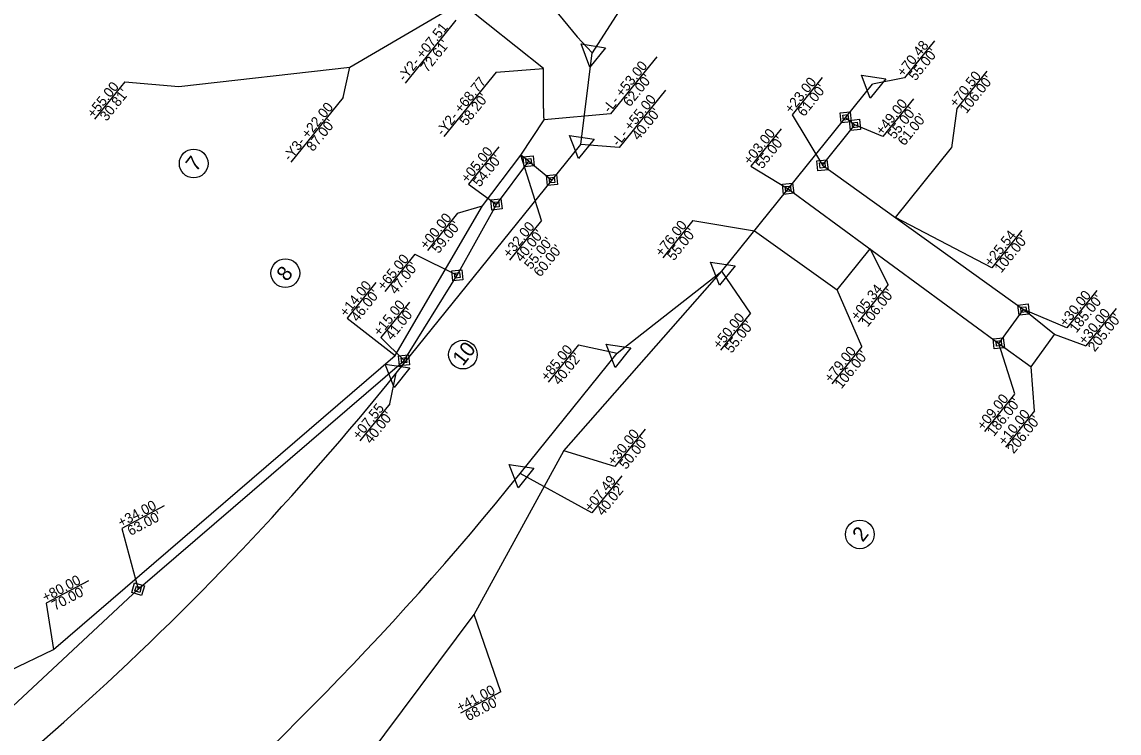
# Model space of a CAD drawing. Extents: x 1487704 to 1489071, y 498271 to 499440.
# Drawn here: x 1488354 to 1488904, y 498758 to 499115 of the extents above; entities that cross this region are included whole.
import ezdxf

# ---------------------------------------------------------------- set-up
doc = ezdxf.new("R2010")
doc.units = 0
for name, color, linetype in [('Prop Easement Construction', 7, 'Continuous'), ('Prop Easement Construction Station Offsets', 7, 'Continuous'), ('Prop Easement Permanent Drainage', 7, 'Continuous'), ('Prop Easement Permanent Drainage Station Offsets', 7, 'Continuous'), ('Prop Easement Temporary Drainage', 7, 'Continuous'), ('Prop Easement Temporary Drainage Station Offsets', 7, 'Continuous'), ('Prop ROW Marker CELL', 7, 'Continuous'), ('Prop ROW Permanent Easement CELL', 7, 'Continuous'), ('Prop ROW RW Lines', 7, 'Continuous'), ('Prop ROW Station Offsets', 7, 'Continuous'), ('Prop ROW Text', 7, 'Continuous')]:
    doc.layers.add(name, color=color, linetype=linetype)

msp = doc.modelspace()

# ---------------------------------------------------------------- linework, layer by layer
at = {"layer": 'Prop Easement Construction'}
for p, q in [((1488518.15, 499091.88), (1488573.75, 499124.4)), ((1488615.46, 499091.23), (1488573.75, 499124.4)), ((1488432.36, 499082.13), (1488518.15, 499091.88)), ((1488604.07, 499047.81), (1488615.7, 499065.41)), ((1488607.97, 499044.67), (1488604.07, 499047.81)), ((1488792.01, 499016.41), (1488820.23, 499051.41)), ((1488721.21, 499009.87), (1488762.79, 498980.19)), ((1488762.79, 498980.19), (1488779.33, 499000.69)), ((1488625.67, 498899.36), (1488704.89, 498989.63)), ((1488871.87, 498957.74), (1488856.3, 498970.29)), ((1488843.9, 498953.32), (1488860.1, 498941.54)), ((1488860.1, 498941.54), (1488871.87, 498957.74)), ((1488580.63, 498817.39), (1488625.67, 498899.36)), ((1488507.15, 498718.97), (1488580.63, 498817.39))]:
    msp.add_line(p, q, dxfattribs=at)
msp.add_spline([(1488615.7, 499065.41), (1488615.68, 499065.76), (1488615.67, 499066.11), (1488615.65, 499066.46), (1488615.64, 499066.82), (1488615.63, 499067.17), (1488615.61, 499067.52), (1488615.6, 499067.87), (1488615.59, 499068.22), (1488615.57, 499068.58), (1488615.56, 499068.93), (1488615.55, 499069.28), (1488615.54, 499069.63), (1488615.53, 499069.98), (1488615.52, 499070.33), (1488615.5, 499070.69), (1488615.49, 499071.04), (1488615.48, 499071.39), (1488615.47, 499071.74), (1488615.47, 499072.09), (1488615.46, 499072.44), (1488615.45, 499072.79), (1488615.44, 499073.14), (1488615.43, 499073.49), (1488615.42, 499073.84), (1488615.42, 499074.19), (1488615.41, 499074.54), (1488615.4, 499074.89), (1488615.4, 499075.24), (1488615.39, 499075.59), (1488615.38, 499075.94), (1488615.38, 499076.29), (1488615.37, 499076.64), (1488615.37, 499076.99), (1488615.36, 499077.34), (1488615.36, 499077.69), (1488615.36, 499078.04), (1488615.35, 499078.39), (1488615.35, 499078.74), (1488615.35, 499079.09), (1488615.35, 499079.44), (1488615.34, 499079.79), (1488615.34, 499080.13), (1488615.34, 499080.48), (1488615.34, 499080.83), (1488615.34, 499081.18), (1488615.34, 499081.53), (1488615.34, 499081.88), (1488615.34, 499082.22), (1488615.34, 499082.57), (1488615.34, 499082.92), (1488615.34, 499083.27), (1488615.34, 499083.61), (1488615.34, 499083.96), (1488615.35, 499084.31), (1488615.35, 499084.66), (1488615.35, 499085), (1488615.36, 499085.35), (1488615.36, 499085.7), (1488615.36, 499086.04), (1488615.37, 499086.39), (1488615.37, 499086.74), (1488615.38, 499087.08), (1488615.38, 499087.43), (1488615.39, 499087.78), (1488615.39, 499088.12), (1488615.4, 499088.47), (1488615.41, 499088.81), (1488615.41, 499089.16), (1488615.42, 499089.5), (1488615.43, 499089.85), (1488615.43, 499090.19), (1488615.44, 499090.54), (1488615.46, 499091.23)], degree=3, dxfattribs=at)
at = {"layer": 'Prop Easement Construction Station Offsets'}
for p, q in [((1488571.39, 499115.4), (1488545.91, 499083.92)), ((1488672.29, 499097.14), (1488649.05, 499068.42)), ((1488591.69, 499089.46), (1488565.47, 499057.05)), ((1488837.94, 499089.85), (1488822.85, 499071.13)), ((1488405.29, 499084.48), (1488390.16, 499065.78)), ((1488514.87, 499076.63), (1488488.64, 499044.21)), ((1488690.33, 499014.98), (1488675.24, 498996.26)), ((1488855.42, 499009.88), (1488840.36, 498991.21)), ((1488788.35, 498982.79), (1488773.3, 498964.12)), ((1488902.73, 498970.82), (1488887.63, 498952.1)), ((1488775.23, 498951.78), (1488760.13, 498933.06)), ((1488861.86, 498919.42), (1488847.21, 498901.25)), ((1488666.35, 498910.29), (1488651.26, 498891.57)), ((1488593.97, 498778.52), (1488573.76, 498767.85))]:
    msp.add_line(p, q, dxfattribs=at)
for points in [[(1488514.87, 499076.63), (1488518.15, 499091.88), (1488518.15, 499091.88)], [(1488591.69, 499089.46), (1488615.46, 499091.23), (1488615.46, 499091.23)], [(1488405.29, 499084.48), (1488432.36, 499082.13)], [(1488649.05, 499068.42), (1488615.7, 499065.41)], [(1488822.85, 499071.13), (1488820.23, 499051.41), (1488820.23, 499051.41)], [(1488690.33, 499014.98), (1488721.21, 499009.87)], [(1488840.36, 498991.21), (1488792.01, 499016.41), (1488792.01, 499016.41)], [(1488788.35, 498982.79), (1488779.33, 499000.69), (1488779.33, 499000.69)], [(1488775.23, 498951.78), (1488762.79, 498980.19), (1488762.79, 498980.19)], [(1488887.77, 498951.99), (1488871.87, 498957.74)], [(1488861.86, 498919.42), (1488860.1, 498941.54)], [(1488651.26, 498891.57), (1488625.67, 498899.36), (1488625.67, 498899.36)], [(1488593.97, 498778.52), (1488580.63, 498817.39), (1488580.63, 498817.39)]]:
    msp.add_lwpolyline(points, dxfattribs=at)
at = {"layer": 'Prop Easement Permanent Drainage'}
for p, q in [((1488755.39, 499042.69), (1488771.71, 499062.92)), ((1488767.04, 499066.69), (1488771.71, 499062.92)), ((1488591.79, 499023.02), (1488607.97, 499044.67)), ((1488607.97, 499044.67), (1488619.64, 499035.25)), ((1488755.39, 499042.69), (1488856.3, 498970.29)), ((1488738.16, 499030.88), (1488843.9, 498953.32)), ((1488572.13, 498987.49), (1488591.79, 499023.02)), ((1488545.42, 498944.81), (1488572.13, 498987.49)), ((1488843.9, 498953.32), (1488856.3, 498970.29)), ((1488411.92, 498830), (1488545.42, 498944.81)), ((1488341.17, 498764.08), (1488411.92, 498830))]:
    msp.add_line(p, q, dxfattribs=at)
at = {"layer": 'Prop Easement Permanent Drainage Station Offsets'}
for p, q in [((1488755.29, 499086.77), (1488740.19, 499068.05)), ((1488801.04, 499076.03), (1488785.76, 499057.08)), ((1488734.63, 499061.02), (1488719.53, 499042.3)), ((1488592.93, 499051.92), (1488577.8, 499033.23)), ((1488550.87, 498998.02), (1488535.75, 498979.32)), ((1488893.11, 498979.81), (1488878.02, 498961.09)), ((1488548.15, 498974.09), (1488533.78, 498956.33)), ((1488851.73, 498927.9), (1488836.64, 498909.18)), ((1488425.03, 498871.78), (1488403.77, 498860.55))]:
    msp.add_line(p, q, dxfattribs=at)
for points in [[(1488740.19, 499068.05), (1488755.39, 499042.69)], [(1488785.76, 499057.08), (1488771.71, 499062.92)], [(1488719.53, 499042.3), (1488738.16, 499030.88)], [(1488577.8, 499033.23), (1488591.79, 499023.02)], [(1488550.87, 498998.02), (1488572.13, 498987.49)], [(1488878.02, 498961.09), (1488856.3, 498970.29), (1488856.3, 498970.29)], [(1488533.78, 498956.33), (1488545.42, 498944.81)], [(1488851.94, 498928.01), (1488843.9, 498953.32), (1488843.9, 498953.32)], [(1488403.77, 498860.55), (1488411.92, 498830)]]:
    msp.add_lwpolyline(points, dxfattribs=at)
at = {"layer": 'Prop Easement Temporary Drainage'}
for p, q in [((1488584.76, 499022.27), (1488604.07, 499047.81)), ((1488540.9, 498947.17), (1488584.76, 499022.27)), ((1488369.59, 498799.74), (1488540.9, 498947.17)), ((1488347.21, 498789.14), (1488369.59, 498799.74))]:
    msp.add_line(p, q, dxfattribs=at)
at = {"layer": 'Prop Easement Temporary Drainage Station Offsets'}
for p, q in [((1488572.24, 499018.6), (1488557.14, 498999.89)), ((1488614.39, 499014.9), (1488598.37, 498995.03)), ((1488531.25, 498983.8), (1488516.91, 498966.01)), ((1488387.05, 498834.26), (1488365.78, 498823.03))]:
    msp.add_line(p, q, dxfattribs=at)
for points in [[(1488614.39, 499014.9), (1488604.07, 499047.81)], [(1488572.24, 499018.6), (1488584.76, 499022.27)], [(1488516.91, 498966.01), (1488540.9, 498947.17)], [(1488365.78, 498823.03), (1488369.59, 498799.74)]]:
    msp.add_lwpolyline(points, dxfattribs=at)
at = {"layer": 'Prop ROW Marker CELL'}
for p, q in [((1488639.84, 499099.01), (1488639.84, 499099.01)), ((1488780.52, 499083.41), (1488780.52, 499083.41)), ((1488767.04, 499066.69), (1488767.04, 499066.69)), ((1488771.71, 499062.92), (1488771.71, 499062.92)), ((1488634.08, 499053.16), (1488634.08, 499053.16)), ((1488607.97, 499044.67), (1488607.97, 499044.67)), ((1488755.39, 499042.69), (1488755.39, 499042.69)), ((1488619.64, 499035.25), (1488619.64, 499035.25)), ((1488738.16, 499030.88), (1488738.16, 499030.88)), ((1488591.79, 499023.02), (1488591.79, 499023.02)), ((1488572.13, 498987.49), (1488572.13, 498987.49)), ((1488704.89, 498989.63), (1488704.89, 498989.63)), ((1488856.3, 498970.29), (1488856.3, 498970.29)), ((1488843.9, 498953.32), (1488843.9, 498953.32)), ((1488652.43, 498948.43), (1488652.43, 498948.43)), ((1488545.42, 498944.81), (1488545.42, 498944.81)), ((1488541.53, 498938.4), (1488541.53, 498938.4)), ((1488603.75, 498888.08), (1488603.75, 498888.08)), ((1488411.92, 498830), (1488411.92, 498830))]:
    msp.add_line(p, q, dxfattribs=at)
for points in [[(1488638.72, 499091.88), (1488634.24, 499103.53), (1488646.57, 499101.61)], [(1488779.4, 499076.29), (1488774.92, 499087.93), (1488787.25, 499086.02)], [(1488632.96, 499046.03), (1488628.48, 499057.68), (1488640.81, 499055.76)], [(1488703.77, 498982.5), (1488699.29, 498994.15), (1488711.62, 498992.23)], [(1488651.31, 498941.31), (1488646.82, 498952.95), (1488659.15, 498951.04)], [(1488540.41, 498931.27), (1488535.93, 498942.92), (1488548.26, 498941)], [(1488602.63, 498880.95), (1488598.15, 498892.6), (1488610.48, 498890.68)]]:
    msp.add_lwpolyline(points, close=True, dxfattribs=at)
at = {"layer": 'Prop ROW Permanent Easement CELL'}
for points in [[(1488764.24, 499068.95), (1488769.3, 499069.49), (1488769.84, 499064.43), (1488764.78, 499063.89)], [(1488765.64, 499067.82), (1488768.17, 499068.09), (1488768.44, 499065.56), (1488765.91, 499065.29)], [(1488768.91, 499065.18), (1488773.97, 499065.73), (1488774.51, 499060.66), (1488769.45, 499060.12)], [(1488770.31, 499064.05), (1488772.84, 499064.32), (1488773.11, 499061.79), (1488770.58, 499061.52)], [(1488605.16, 499046.93), (1488610.23, 499047.47), (1488610.77, 499042.41), (1488605.71, 499041.87)], [(1488606.56, 499045.8), (1488609.1, 499046.07), (1488609.37, 499043.54), (1488606.84, 499043.27)], [(1488752.58, 499044.94), (1488757.65, 499045.49), (1488758.19, 499040.43), (1488753.13, 499039.88)], [(1488753.99, 499043.82), (1488756.52, 499044.09), (1488756.79, 499041.56), (1488754.26, 499041.28)], [(1488616.84, 499037.51), (1488621.9, 499038.05), (1488622.44, 499032.99), (1488617.38, 499032.45)], [(1488618.24, 499036.38), (1488620.77, 499036.65), (1488621.04, 499034.12), (1488618.51, 499033.85)], [(1488735.36, 499033.14), (1488740.42, 499033.69), (1488740.96, 499028.62), (1488735.9, 499028.08)], [(1488736.76, 499032.01), (1488739.29, 499032.28), (1488739.56, 499029.75), (1488737.03, 499029.48)], [(1488588.99, 499025.28), (1488594.05, 499025.83), (1488594.6, 499020.76), (1488589.53, 499020.22)], [(1488590.39, 499024.15), (1488592.92, 499024.42), (1488593.2, 499021.89), (1488590.66, 499021.62)], [(1488569.33, 498989.75), (1488574.39, 498990.29), (1488574.94, 498985.23), (1488569.87, 498984.69)], [(1488570.73, 498988.62), (1488573.26, 498988.89), (1488573.53, 498986.36), (1488571, 498986.09)], [(1488853.5, 498972.55), (1488858.56, 498973.1), (1488859.11, 498968.03), (1488854.04, 498967.49)], [(1488854.9, 498971.42), (1488857.43, 498971.69), (1488857.71, 498969.16), (1488855.17, 498968.89)], [(1488841.1, 498955.58), (1488846.16, 498956.12), (1488846.7, 498951.06), (1488841.64, 498950.52)], [(1488842.5, 498954.45), (1488845.03, 498954.72), (1488845.3, 498952.19), (1488842.77, 498951.92)], [(1488542.61, 498947.07), (1488547.68, 498947.61), (1488548.22, 498942.55), (1488543.16, 498942)], [(1488544.02, 498945.94), (1488546.55, 498946.21), (1488546.82, 498943.68), (1488544.29, 498943.4)], [(1488410.24, 498833.18), (1488415.1, 498831.68), (1488413.6, 498826.82), (1488408.74, 498828.32)], [(1488411.08, 498831.59), (1488413.51, 498830.84), (1488412.76, 498828.41), (1488410.33, 498829.16)]]:
    msp.add_lwpolyline(points, close=True, dxfattribs=at)
at = {"layer": 'Prop ROW RW Lines'}
for p, q in [((1488634.08, 499053.16), (1488639.84, 499099.01)), ((1488704.89, 498989.63), (1488780.52, 499083.41)), ((1488541.53, 498938.4), (1488634.08, 499053.16)), ((1488652.43, 498948.43), (1488704.89, 498989.63)), ((1488603.75, 498888.08), (1488652.43, 498948.43))]:
    msp.add_line(p, q, dxfattribs=at)
for centre, radius, start, end in [((1488809.02, 499262.12), 235, 195.2846, 223.9537), ((1487403.1, 499856.48), 1462.5, 302.71583, 321.11571), ((1487403.1, 499856.44), 1542.5, 297.83218, 321.11298)]:
    msp.add_arc(centre, radius, start, end, dxfattribs=at)
at = {"layer": 'Prop ROW Station Offsets'}
for p, q in [((1488811.6, 499105.18), (1488796.55, 499086.52)), ((1488676.67, 499080.31), (1488653.43, 499051.59)), ((1488719.25, 498968.57), (1488704.15, 498949.85)), ((1488632.92, 498952.55), (1488617.82, 498933.83)), ((1488538.26, 498923.02), (1488523.27, 498904.43)), ((1488654.73, 498886.92), (1488639.71, 498868.3))]:
    msp.add_line(p, q, dxfattribs=at)
for points in [[(1488668.08, 499143.3), (1488639.84, 499099.01)], [(1488796.55, 499086.52), (1488780.52, 499083.41), (1488780.52, 499083.41)], [(1488653.43, 499051.59), (1488634.08, 499053.16)], [(1488719.25, 498968.57), (1488704.89, 498989.63), (1488704.89, 498989.63)], [(1488632.92, 498952.55), (1488652.43, 498948.43), (1488652.43, 498948.43)], [(1488538.26, 498923.02), (1488541.53, 498938.4)], [(1488639.71, 498868.3), (1488603.75, 498888.08)]]:
    msp.add_lwpolyline(points, dxfattribs=at)
at = {"layer": 'Prop ROW Text'}
for p, q in [((1488439.86, 499043.58), (1488439.86, 499043.58)), ((1488485.85, 498988.57), (1488485.85, 498988.57)), ((1488574.98, 498947.7), (1488574.98, 498947.7)), ((1488774.15, 498857.51), (1488774.15, 498857.51))]:
    msp.add_line(p, q, dxfattribs=at)
for centre in [(1488439.86, 499043.58), (1488485.85, 498988.57), (1488574.98, 498947.7), (1488774.15, 498857.51)]:
    msp.add_circle(centre, 7.2, dxfattribs=at)

# ---------------------------------------------------------------- texts
at = {"layer": 'Prop Easement Construction Station Offsets'}
for s, rotation, p in [('-Y2- +07.51', 51.0257, (1488545.68, 499084.42)), ("72.61'", 51.0257, (1488557.09, 499088.98)), ('-L- +53.00', 51.0257, (1488648.57, 499068.62)), ('-Y2- +68.77', 51.0257, (1488564.91, 499057.16)), ("62.00'", 51.0257, (1488658.73, 499071.64)), ('+70.50', 51.1156, (1488822.37, 499071.33)), ("106.00'", 51.1156, (1488827.61, 499068.27)), ('+55.00', 51.0257, (1488389.68, 499065.98)), ("30.81'", 51.0257, (1488396.16, 499064.45)), ('-Y3- +22.00', 51.0257, (1488488.16, 499044.41)), ("58.20'", 51.0257, (1488576.64, 499062.11)), ("87.00'", 51.0257, (1488499.81, 499049.28)), ('+76.00', 51.1156, (1488674.76, 498996.46)), ("55.00'", 51.1156, (1488680.86, 498994.47)), ('+25.54', 51.1156, (1488839.95, 498991.49)), ("106.00'", 51.1156, (1488845.1, 498988.33)), ('+05.34', 51.1156, (1488772.88, 498964.4)), ("106.00'", 51.1156, (1488778.04, 498961.23)), ('+30.00', 51.1156, (1488887.15, 498952.3)), ("205.00'", 51.1156, (1488892.02, 498948.77)), ('+79.00', 51.1156, (1488759.65, 498933.26)), ("106.00'", 51.1156, (1488764.89, 498930.2)), ('+10.00', 51.1156, (1488846.88, 498901.64)), ("206.00'", 51.1156, (1488851.37, 498897.65)), ('+30.00', 51.1156, (1488650.78, 498891.77)), ("50.00'", 51.1156, (1488656.88, 498889.78)), ('+41.00', 27.8351, (1488573.4, 498768.22)), ("68.00'", 27.8351, (1488577.69, 498763.7))]:
    msp.add_text(s, height=5, rotation=rotation, dxfattribs=at).set_placement(p)
at = {"layer": 'Prop Easement Permanent Drainage Station Offsets'}
for s, rotation, p in [('+23.00', 51.1156, (1488739.71, 499068.25)), ("61.00'", 51.1156, (1488746.19, 499066.73)), ('+49.00', 51.1156, (1488785.37, 499057.39)), ("55.00'", 51.1156, (1488791.47, 499055.41)), ("61.00'", 51.1156, (1488796.52, 499052.11)), ('+03.00', 51.1156, (1488719.05, 499042.5)), ("55.00'", 51.1156, (1488725.16, 499040.51)), ('+05.00', 51.0257, (1488577.32, 499033.43)), ("54.00'", 51.0257, (1488583.42, 499031.43)), ('+65.00', 51.0257, (1488535.27, 498979.52)), ("47.00'", 51.0257, (1488541.37, 498977.53)), ('+15.00', 51.0257, (1488533.3, 498956.53)), ('+30.00', 51.1156, (1488877.53, 498961.29)), ("185.00'", 51.1156, (1488882.77, 498958.23)), ("41.00'", 51.0257, (1488539.4, 498954.53)), ('+09.00', 51.1156, (1488836.16, 498909.38)), ("186.00'", 51.1156, (1488841.39, 498906.32)), ('+34.00', 27.8351, (1488403.4, 498860.92)), ("63.00'", 27.8351, (1488408.22, 498856.68))]:
    msp.add_text(s, height=5, rotation=rotation, dxfattribs=at).set_placement(p)
at = {"layer": 'Prop Easement Temporary Drainage Station Offsets'}
for s, rotation, p in [('+00.00', 51.1156, (1488556.66, 499000.09)), ("59.00'", 51.1156, (1488562.77, 498998.1)), ('+32.00', 51.1156, (1488598.35, 498995.8)), ("40.00'", 51.1156, (1488604.46, 498993.81)), ("55.00'", 51.1156, (1488609.13, 498990.05)), ("60.00'", 51.1156, (1488613.8, 498986.28)), ('+14.00', 51.1156, (1488516.43, 498966.21)), ("46.00'", 51.1156, (1488522.15, 498963.76)), ('+80.00', 27.8351, (1488365.42, 498823.4)), ("70.00'", 27.8351, (1488370.24, 498819.17))]:
    msp.add_text(s, height=5, rotation=rotation, dxfattribs=at).set_placement(p)
at = {"layer": 'Prop ROW Station Offsets'}
for s, rotation, p in [('+70.48', 51.1156, (1488796.05, 499086.69)), ("55.00'", 51.1156, (1488802.15, 499084.7)), ('-L- +55.00', 51.0257, (1488652.95, 499051.79)), ("40.00'", 51.0257, (1488663.11, 499054.81)), ('+50.00', 51.1156, (1488703.67, 498950.05)), ("55.00'", 51.1156, (1488709.78, 498948.07)), ('+85.00', 51.1156, (1488617.34, 498934.03)), ("40.02'", 51.1156, (1488623.44, 498932.04)), ('+07.55', 51.1156, (1488522.8, 498904.64)), ("40.00'", 51.1156, (1488528.84, 498902.58)), ('+07.49', 51.1156, (1488639.22, 498868.48)), ("40.02'", 51.1156, (1488645.3, 498866.46))]:
    msp.add_text(s, height=5, rotation=rotation, dxfattribs=at).set_placement(p)
at = {"layer": 'Prop ROW Text'}
for s, p in [('7', (1488441.09, 499039.08)), ('8', (1488486.66, 498983.95)), ('10', (1488574.96, 498941.6)), ('2', (1488775.59, 498853.27))]:
    msp.add_text(s, height=7.5, rotation=51.8667, dxfattribs=at).set_placement(p)

doc.saveas('drawing.dxf')
